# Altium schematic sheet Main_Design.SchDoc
size A4; SheetNumber: 1; SheetTotal: 2
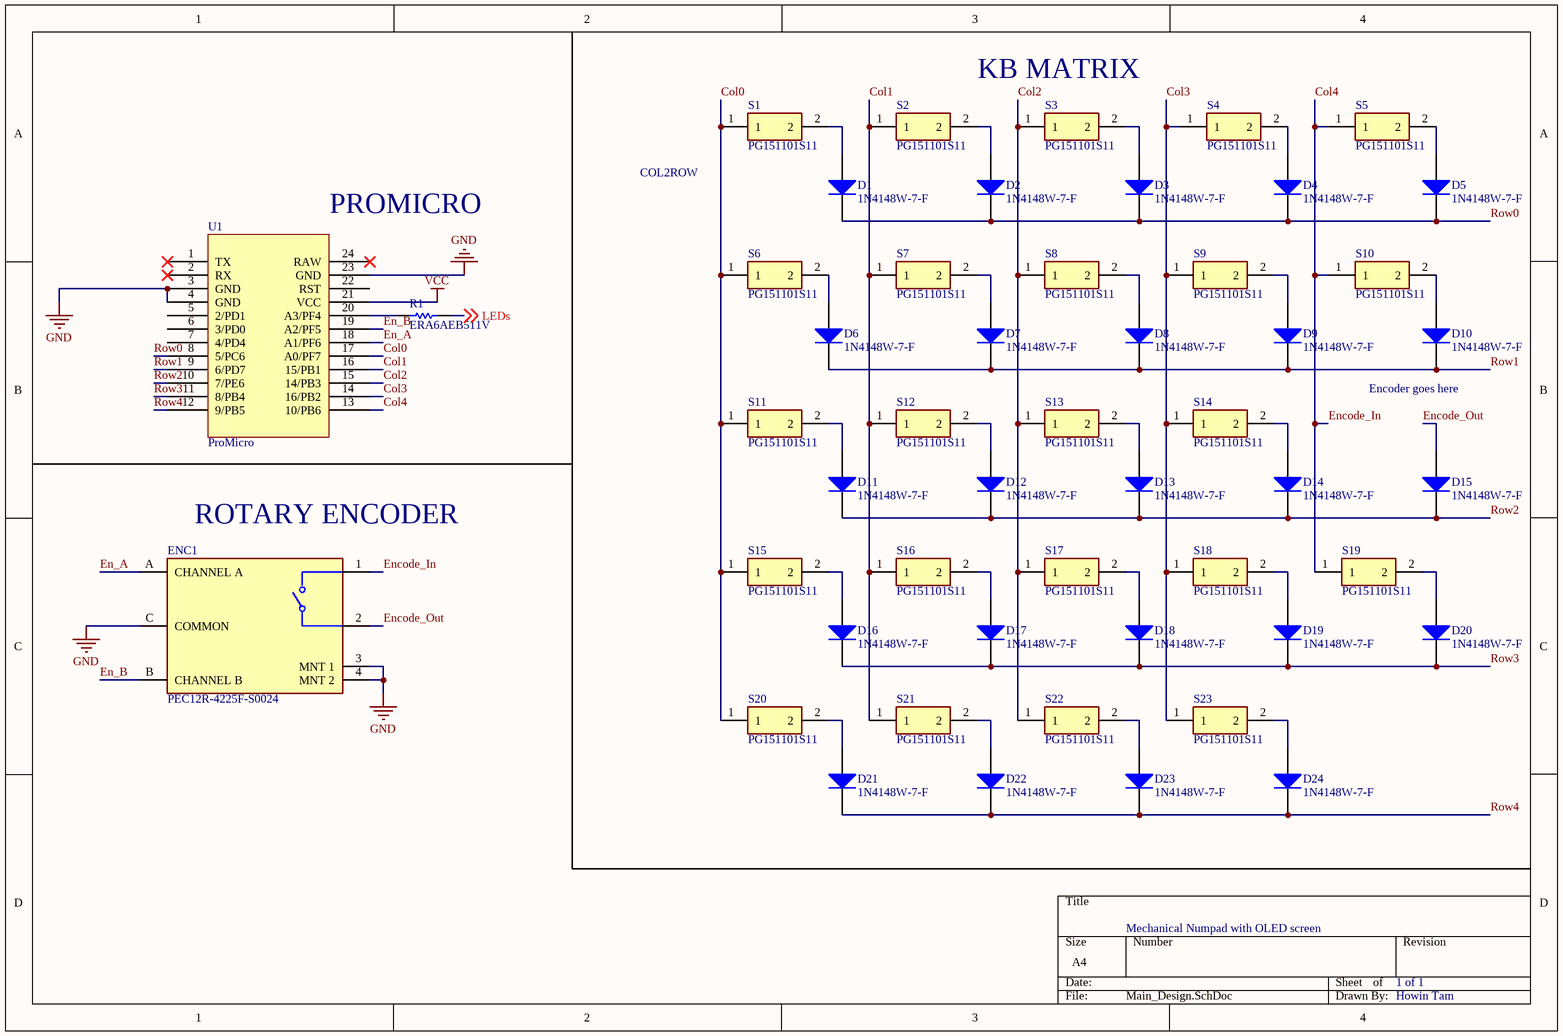
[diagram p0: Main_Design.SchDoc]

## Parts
D1  1N4148W-7-F  [DIOD-SOD123-2_V]
D2  1N4148W-7-F  [DIOD-SOD123-2_V]
D3  1N4148W-7-F  [DIOD-SOD123-2_V]
D4  1N4148W-7-F  [DIOD-SOD123-2_V]
D5  1N4148W-7-F  [DIOD-SOD123-2_V]
D6  1N4148W-7-F  [DIOD-SOD123-2_V]
D7  1N4148W-7-F  [DIOD-SOD123-2_V]
D8  1N4148W-7-F  [DIOD-SOD123-2_V]
D9  1N4148W-7-F  [DIOD-SOD123-2_V]
D10  1N4148W-7-F  [DIOD-SOD123-2_V]
D11  1N4148W-7-F  [DIOD-SOD123-2_V]
D12  1N4148W-7-F  [DIOD-SOD123-2_V]
D13  1N4148W-7-F  [DIOD-SOD123-2_V]
D14  1N4148W-7-F  [DIOD-SOD123-2_V]
D15  1N4148W-7-F  [DIOD-SOD123-2_V]
D16  1N4148W-7-F  [DIOD-SOD123-2_V]
D17  1N4148W-7-F  [DIOD-SOD123-2_V]
D18  1N4148W-7-F  [DIOD-SOD123-2_V]
D19  1N4148W-7-F  [DIOD-SOD123-2_V]
D20  1N4148W-7-F  [DIOD-SOD123-2_V]
D21  1N4148W-7-F  [DIOD-SOD123-2_V]
D22  1N4148W-7-F  [DIOD-SOD123-2_V]
D23  1N4148W-7-F  [DIOD-SOD123-2_V]
D24  1N4148W-7-F  [DIOD-SOD123-2_V]
ENC1  PEC12R-4225F-S0024  [FP-PEC12R-4225F-S0024-MFG]
R1  ERA6AEB511V  [RESC2013X60X40ML20T25]
S1  PG151101S11  [SW_PG151101S11]
S2  PG151101S11  [SW_PG151101S11]
S3  PG151101S11  [SW_PG151101S11]
S4  PG151101S11  [SW_PG151101S11]
S5  PG151101S11  [SW_PG151101S11]
S6  PG151101S11  [SW_PG151101S11]
S7  PG151101S11  [SW_PG151101S11]
S8  PG151101S11  [SW_PG151101S11]
S9  PG151101S11  [SW_PG151101S11]
S10  PG151101S11  [SW_PG151101S11]
S11  PG151101S11  [SW_PG151101S11]
S12  PG151101S11  [SW_PG151101S11]
S13  PG151101S11  [SW_PG151101S11]
S14  PG151101S11  [SW_PG151101S11]
S15  PG151101S11  [SW_PG151101S11]
S16  PG151101S11  [SW_PG151101S11]
S17  PG151101S11  [SW_PG151101S11]
S18  PG151101S11  [SW_PG151101S11]
S19  PG151101S11  [SW_PG151101S11]
S20  PG151101S11  [SW_PG151101S11]
S21  PG151101S11  [SW_PG151101S11]
S22  PG151101S11  [SW_PG151101S11]
S23  PG151101S11  [SW_PG151101S11]
U1  ProMicro  [PCBComponent_1]

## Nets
GND: ENC1.3(MNT_1) ENC1.4(MNT_2) ENC1.C(COMMON) U1.3(GND) U1.4(GND) U1.23(GND)
VCC: U1.21(VCC)
Col0: S1.1 S6.1 S11.1 S15.1 S20.1 U1.17(A0/PF7)
Col1: S2.1 S7.1 S12.1 S16.1 S21.1 U1.16(15/PB1)
Col2: S3.1 S8.1 S13.1 S17.1 S22.1 U1.15(14/PB3)
Col3: S4.1 S9.1 S14.1 S18.1 S23.1 U1.14(16/PB2)
Col4: ENC1.1 S5.1 S10.1 S19.1 U1.13(10/PB6)  [also labelled Encode_In]
En_A: ENC1.A(CHANNEL_A) U1.18(A1/PF6)
En_B: ENC1.B(CHANNEL_B) U1.19(A2/PF5)
Encode_Out: D15.1(A) ENC1.2
LEDs: R1.2 ; off-sheet LEDs
Row0: D1.2(K) D2.2(K) D3.2(K) D4.2(K) D5.2(K) U1.8(5/PC6)
Row1: D6.2(K) D7.2(K) D8.2(K) D9.2(K) D10.2(K) U1.9(6/PD7)
Row2: D11.2(K) D12.2(K) D13.2(K) D14.2(K) D15.2(K) U1.10(7/PE6)
Row3: D16.2(K) D17.2(K) D18.2(K) D19.2(K) D20.2(K) U1.11(8/PB4)
Row4: D21.2(K) D22.2(K) D23.2(K) D24.2(K) U1.12(9/PB5)
NetD1_1: D1.1(A) S1.2
NetD2_1: D2.1(A) S2.2
NetD3_1: D3.1(A) S3.2
NetD4_1: D4.1(A) S4.2
NetD5_1: D5.1(A) S5.2
NetD6_1: D6.1(A) S6.2
NetD7_1: D7.1(A) S7.2
NetD8_1: D8.1(A) S8.2
NetD9_1: D9.1(A) S9.2
NetD10_1: D10.1(A) S10.2
NetD11_1: D11.1(A) S11.2
NetD12_1: D12.1(A) S12.2
NetD13_1: D13.1(A) S13.2
NetD14_1: D14.1(A) S14.2
NetD16_1: D16.1(A) S15.2
NetD17_1: D17.1(A) S16.2
NetD18_1: D18.1(A) S17.2
NetD19_1: D19.1(A) S18.2
NetD20_1: D20.1(A) S19.2
NetD21_1: D21.1(A) S20.2
NetD22_1: D22.1(A) S21.2
NetD23_1: D23.1(A) S22.2
NetD24_1: D24.1(A) S23.2
NetR1_1: R1.1 U1.20(A3/PF4)

Not connected (* = marked no-connect by the designer): U1 1(TX)* 2(RX)* 5(2/PD1) 6(3/PD0) 7(4/PD4) 22(RST) 24(RAW)*

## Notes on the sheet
- KB MATRIX
- COL2ROW
- (near U1) PROMICRO
- (near D10) Encoder goes here
- (near ENC1) ROTARY ENCODER
- Mechanical Numpad with OLED screen
- 1 of 1
- Howin Tam

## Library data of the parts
D1-D24 = CMP-2000-04932-2: Fast Switching Diode, 100 V, 0.15 A, -65 to 150 degC, 2-Pin?SOD123, RoHS, Tape and Reel; Recovery Time: 4ns; Brand: DiodesIncorporated; Unit Weight: 0.000353oz; Max Surge Current: 2A; Peak Reverse Voltage: 100V; Ir - Reverse Current: 1uA; Vf - Forward Voltage: 1.25V; Configuration: Single; If - Forward Current: 0.15A
ENC1 = CMP-07421-000041-1: ROTARY ENCODER MECHANICAL 24PPR; Built in Switch: Yes; Hole Diameter: 1mm; Number of Channels: 2; Pulses per Revolution: 24; Output Type: Quadrature
R1 = CMP-2001-00648-1: Manufacturer: Panasonic
S1-S23 = PG151101S11: Keyswitch; MF: Kailh
U1 = Component_1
